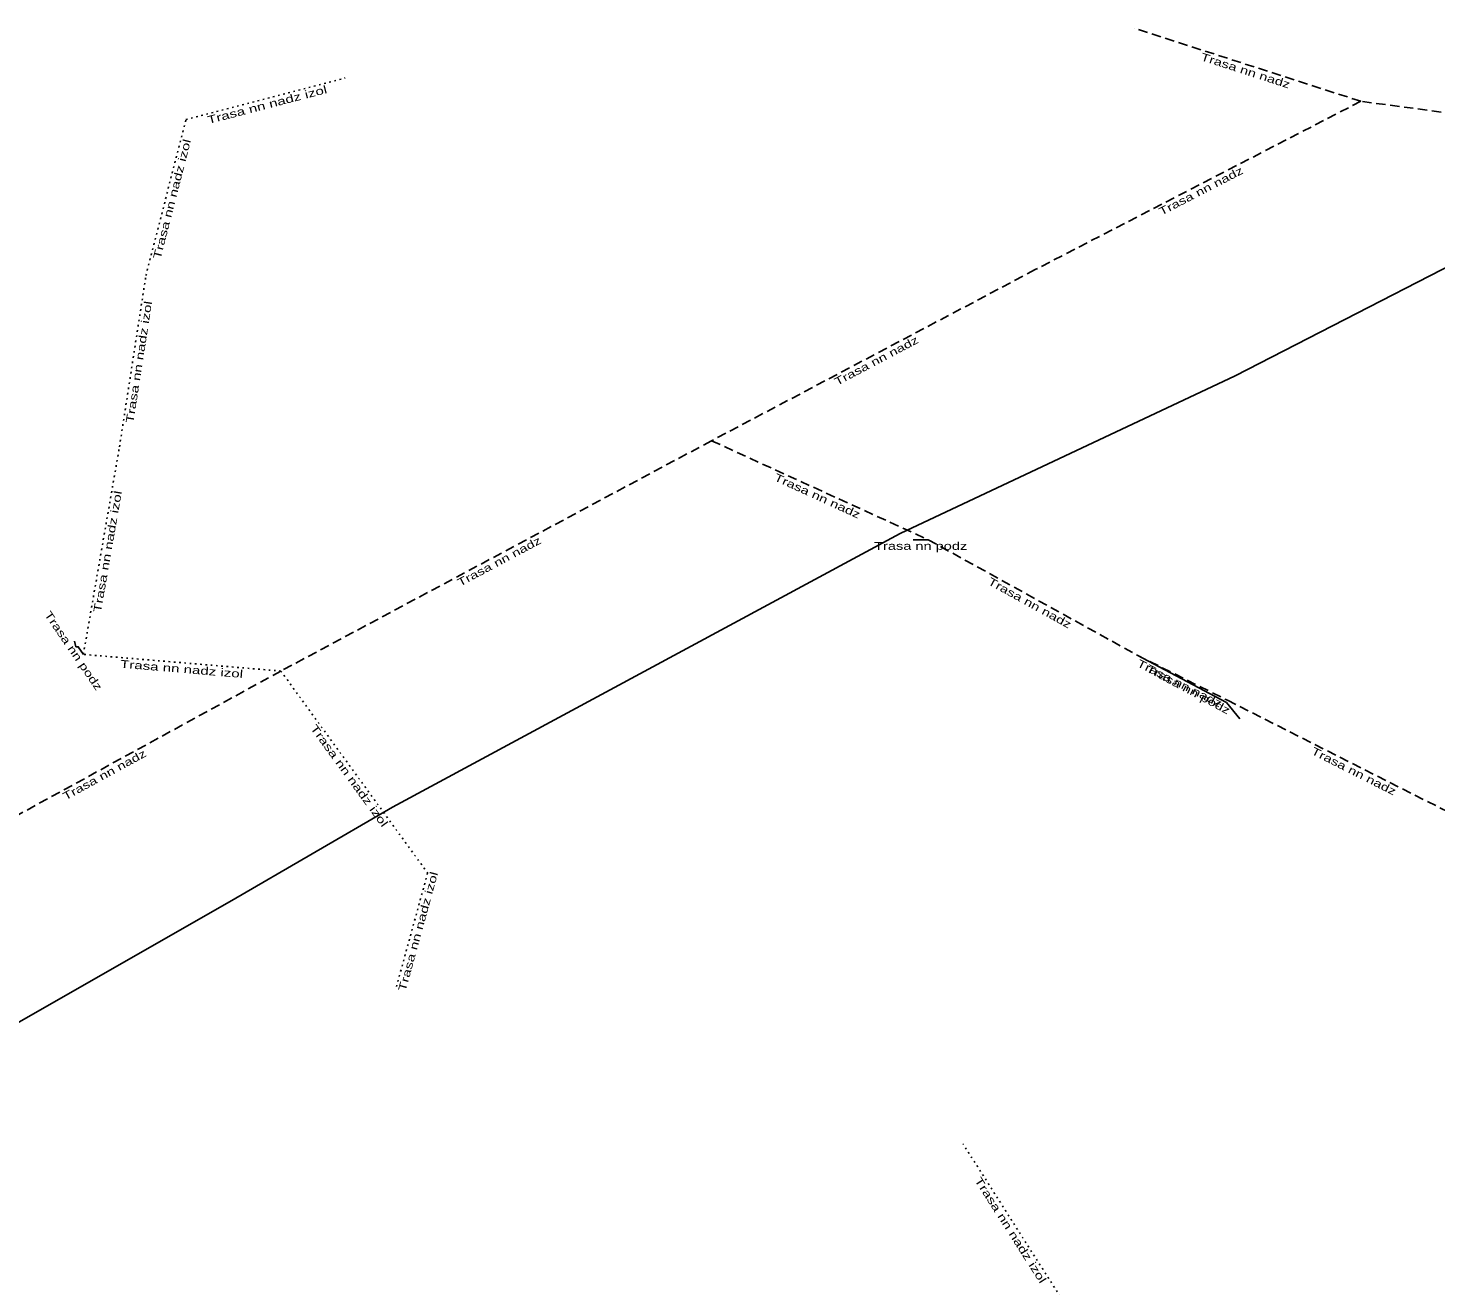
# Model space of a CAD drawing. Extents: x -733620 to -732615, y -1025255 to -1024617.
# Drawn here: x -733116.1 to -733025.6, y -1024868.1 to -1024787.3 of the extents above; entities that cross this region are included whole.
import ezdxf
from ezdxf.enums import TextEntityAlignment as Align

# ---------------------------------------------------------------- set-up
doc = ezdxf.new("R2010")
doc.units = 0
doc.header["$LTSCALE"] = 0.2
doc.linetypes.add('DOTTED', pattern=[1.5, 0.3, -1.2])
doc.linetypes.add('MEDIUM_DASHED', pattern=[4.5, 3, -1.5])
doc.layers.add('11', color=7, linetype='MEDIUM_DASHED', lineweight=25)
doc.layers.add('21', color=7, linetype='Continuous', lineweight=25)
doc.layers.add('20', color=7, linetype='Continuous')

msp = doc.modelspace()

# ---------------------------------------------------------------- linework, layer by layer
at = {"layer": '11'}
for p, q in [((-733030.43, -1024792), (-733045, -1024787.3)), ((-733030.43, -1024792), (-733051.35, -1024802.82)), ((-733011, -1024794.6), (-733030.43, -1024792)), ((-733051.35, -1024802.82), (-733072.15, -1024813.82)), ((-733072.15, -1024813.82), (-733099.83, -1024828.62)), ((-733072.15, -1024813.82), (-733058.23, -1024820.18)), ((-733058.23, -1024820.18), (-733044.8, -1024827.6)), ((-733044.8, -1024827.6), (-733039, -1024830.5)), ((-733099.83, -1024828.62), (-733122.89, -1024841.25)), ((-733039, -1024830.5), (-733022.4, -1024838.9))]:
    msp.add_line(p, q, dxfattribs=at)
at = {"layer": '11', "linetype": 'DOTTED'}
for p, q in [((-733105.93, -1024793.17), (-733095.7, -1024790.5)), ((-733108.5, -1024803.2), (-733105.93, -1024793.17)), ((-733110.2, -1024814.2), (-733108.5, -1024803.2)), ((-733112.52, -1024827.55), (-733110.2, -1024814.2)), ((-733099.83, -1024828.62), (-733112.52, -1024827.55)), ((-733099.83, -1024828.62), (-733090.4, -1024841.6)), ((-733090.4, -1024841.6), (-733092.4, -1024848.9)), ((-733049.21, -1024869.67), (-733056, -1024859))]:
    msp.add_line(p, q, dxfattribs=at)
at = {"layer": '11', "linetype": 'Continuous'}
msp.add_line((-733059.2, -1024820.18), (-733058.23, -1024820.18), dxfattribs=at)
for points in [[(-733112.52, -1024827.55), (-733112.855, -1024827.059), (-733113, -1024827.059), (-733113.1, -1024826.7)], [(-733044.8, -1024827.6), (-733039.07, -1024830.65), (-733038.2, -1024831.7)]]:
    msp.add_lwpolyline(points, dxfattribs=at)
at = {"layer": '21'}
msp.add_lwpolyline([(-733124.635, -1024855.725), (-733102.986, -1024843.362), (-733092.656, -1024837.362), (-733060.022, -1024819.78), (-733038.504, -1024809.639), (-733017.396, -1024798.81), (-733013.231, -1024795.794), (-733011.375, -1024794.322), (-733010.985, -1024793.85)], dxfattribs=at)

# ---------------------------------------------------------------- texts
at = {"layer": '20'}
for s, rotation, width, p in [('Trasa nn nadz', 342.121, 1.4, (-733037.9143, -1024790.2681)), ('Trasa nn nadz izol', 14.628, 1.45, (-733100.6506, -1024792.463)), ('Trasa nn nadz izol', 75.628, 1.45, (-733106.5849, -1024798.3456)), ('Trasa nn nadz', 27.348, 1.4, (-733040.5903, -1024797.9866)), ('Trasa nn nadz izol', 81.215, 1.45, (-733108.7075, -1024808.7987)), ('Trasa nn nadz', 27.872, 1.4, (-733061.4454, -1024808.8945)), ('Trasa nn nadz', 335.445, 1.4, (-733065.4594, -1024817.5915)), ('Trasa nn nadz izol', 80.141, 1.45, (-733110.7195, -1024820.9853)), ('Trasa nn nadz', 28.133, 1.4, (-733085.6824, -1024821.7925)), ('Trasa nn nadz', 331.08, 1.4, (-733051.8284, -1024824.4582)), ('Trasa nn podz', 304.305, 1.4, (-733113.3704, -1024827.4566)), ('Trasa nn nadz izol', 355.18, 1.45, (-733106.2295, -1024828.7323)), ('Trasa nn nadz', 333.435, 1.4, (-733042.1903, -1024829.6308)), ('Trasa nn podz', 331.974, 1.4, (-733041.638, -1024830.0181)), ('Trasa nn nadz izol', 305.998, 1.45, (-733095.6404, -1024835.4916)), ('Trasa nn nadz', 333.159, 1.4, (-733030.9934, -1024835.2792)), ('Trasa nn nadz', 28.71, 1.4, (-733111.0466, -1024835.5048)), ('Trasa nn nadz izol', 74.678, 1.45, (-733090.7728, -1024845.4216)), ('Trasa nn nadz izol', 302.471, 1.45, (-733053.1525, -1024864.6833))]:
    msp.add_text(s, height=0.5, rotation=rotation, dxfattribs=dict(at, width=width)).set_placement(p, align=Align.CENTER)
at = {"layer": '20', "width": 1.4}
msp.add_text('Trasa nn podz', height=0.5, dxfattribs=at).set_placement((-733058.7145, -1024820.83), align=Align.CENTER)

doc.saveas('drawing.dxf')
